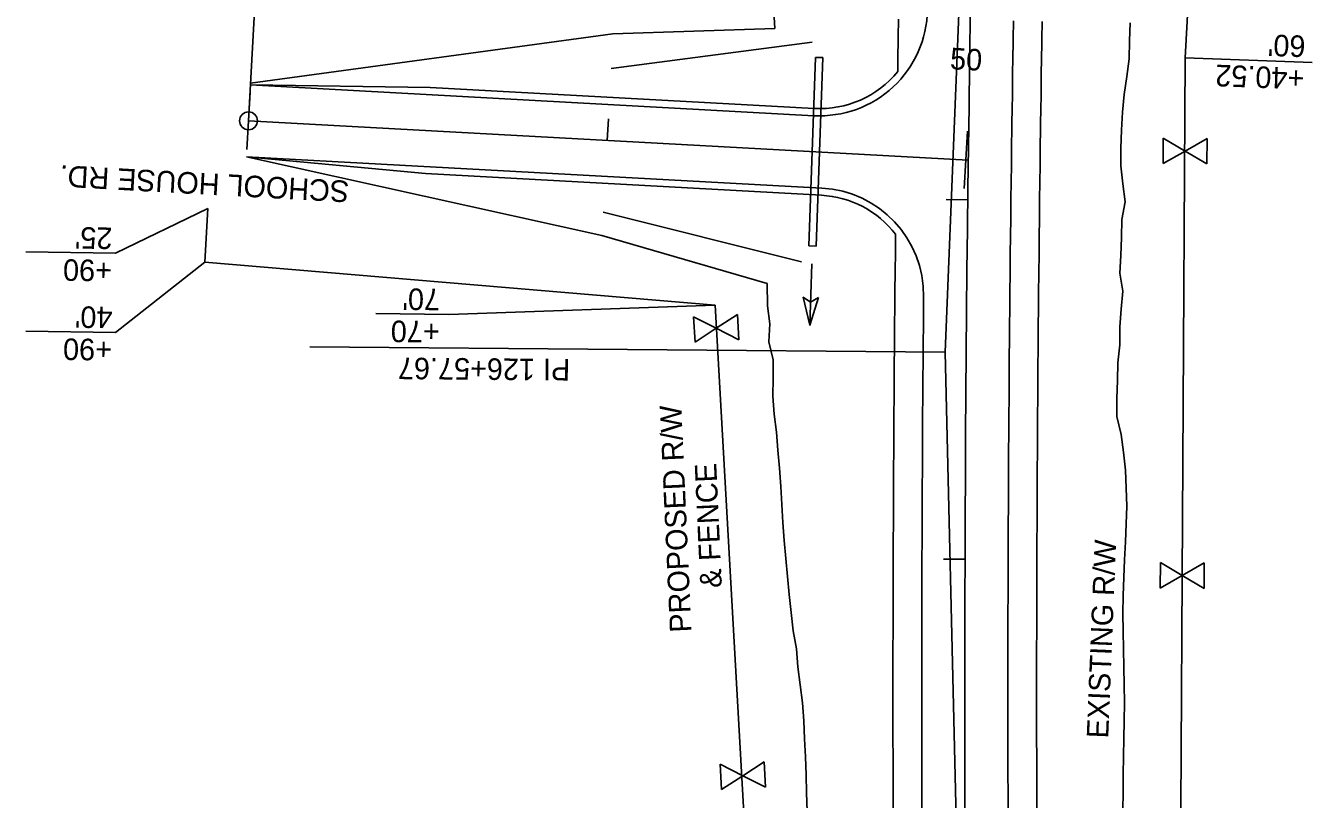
# Model space of a CAD drawing. Extents: x 634057 to 641016, y 287858 to 292331.
# Drawn here: x 634057.5 to 634415.7, y 291397.6 to 291613 of the extents above; entities that cross this region are included whole.
import ezdxf

# ---------------------------------------------------------------- set-up
doc = ezdxf.new("R2010")
doc.units = 0
for name, color, linetype in [('53', 7, 'Continuous'), ('PROPOSED SPECIAL DITCHES', 7, 'Continuous'), ('R_50 Horz Alg PC PI PT', 7, 'Continuous'), ('R_50 Horz Alg Stations', 7, 'Continuous'), ('R_50 Horz Alg Ticks', 7, 'Continuous'), ('R_Horz Alg', 7, 'Continuous'), ('R_No Plot', 7, 'Continuous'), ('R_Proposed Const Limits', 7, 'Continuous'), ('R_Proposed Road', 7, 'Continuous'), ('R_Proposed Shoulder', 7, 'Continuous'), ('R_ROW', 7, 'Continuous'), ('R_Water', 7, 'Continuous')]:
    doc.layers.add(name, color=color, linetype=linetype)

msp = doc.modelspace()

# ---------------------------------------------------------------- linework, layer by layer
at = {"layer": '53'}
for p, q in [((634415.68, 291602.72), (634380.33, 291604.07)), ((634108.17, 291562.09), (634082.44, 291549.65)), ((634082.44, 291549.65), (634057.49, 291550.03)), ((634107.36, 291547.11), (634082.44, 291527.61)), ((634175.28, 291532.62), (634154.97, 291532.84)), ((634249.46, 291535.15), (634175.28, 291532.62)), ((634082.44, 291527.61), (634057.49, 291527.99))]:
    msp.add_line(p, q, dxfattribs=at)
at = {"layer": 'PROPOSED SPECIAL DITCHES'}
for points in [[(634220.46, 291601.03), (634276.46, 291608.43)], [(634218.28, 291561.09), (634273.44, 291547.26)]]:
    msp.add_lwpolyline(points, dxfattribs=at)
at = {"layer": 'R_50 Horz Alg PC PI PT'}
for points in [[(634313.51, 291522.09), (634328.23, 291887.62)], [(634119.52, 291586.5), (634126.28, 291710.5)], [(634313.51, 291522.09), (634136.57, 291523.57)], [(634322.13, 291156.36), (634313.51, 291522.09)]]:
    msp.add_lwpolyline(points, dxfattribs=at)
msp.add_circle((634119.52, 291586.5), 2.5, dxfattribs=at)
at = {"layer": 'R_50 Horz Alg Ticks'}
for points in [[(634119.96, 291594.49), (634119.08, 291578.52)], [(634119.96, 291594.49), (634119.08, 291578.52)], [(634219.7, 291587.05), (634219.37, 291581.06)], [(634319.66, 291583.6), (634318.79, 291567.62)], [(634313.78, 291564.56), (634319.78, 291564.49)], [(634313.01, 291464.51), (634319.01, 291464.49)]]:
    msp.add_lwpolyline(points, dxfattribs=at)
at = {"layer": 'R_Horz Alg'}
msp.add_lwpolyline([(634319.92, 291575.57), (634119.52, 291586.5)], dxfattribs=at)
msp.add_arc((645778.1, 291426.39), 11459.16, 177.693224, 181.350269, dxfattribs=at)
at = {"layer": 'R_Proposed Const Limits'}
for points in [[(634266.02, 291612.22), (634265.87, 291615.38)], [(634220.99, 291610.74), (634120.07, 291596.99)], [(634220.99, 291610.74), (634266.02, 291612.22)], [(634365.01, 291613.75), (634364.83, 291608.78), (634364.73, 291603.8), (634364.04, 291598.82), (634363.35, 291593.85), (634362.88, 291588.88), (634362.53, 291583.9), (634362.42, 291578.92), (634362.38, 291573.94), (634362.93, 291568.95), (634363.57, 291563.96), (634362.71, 291558.99), (634362.57, 291554.01), (634362.34, 291549.03), (634362.08, 291544.05), (634362.98, 291539.06), (634362.5, 291534.09), (634362.07, 291529.11), (634362.15, 291524.13), (634361.58, 291519.15), (634361.46, 291514.17), (634361.28, 291509.19), (634361.23, 291504.21), (634362.46, 291499.22), (634363.1, 291494.23), (634363.64, 291489.25), (634363.88, 291484.27), (634364.05, 291479.28), (634363.86, 291474.3), (634363.64, 291469.32), (634363.45, 291464.34), (634363.23, 291459.36), (634363.02, 291454.38), (634362.92, 291449.4), (634363.01, 291444.42), (634363.1, 291439.44), (634363.2, 291434.46), (634363.3, 291429.48), (634363.4, 291424.5), (634363.33, 291419.52), (634363.23, 291414.54), (634363.14, 291409.56), (634363.07, 291404.58), (634363.04, 291399.6), (634362.98, 291394.62)], [(634217.93, 291554.57), (634118.98, 291576.52)], [(634217.93, 291554.57), (634263.91, 291541.25)], [(634275.07, 291394.37), (634274.91, 291399.39), (634274.77, 291404.41), (634274.56, 291409.43), (634274.29, 291414.45), (634274.16, 291419.47), (634273.8, 291424.49), (634273.13, 291429.51), (634272.46, 291434.53), (634272.12, 291439.55), (634271.2, 291444.57), (634270.58, 291449.59), (634270.06, 291454.61), (634269.6, 291459.64), (634269.1, 291464.66), (634268.61, 291469.68), (634268.25, 291474.71), (634268.03, 291479.73), (634267.75, 291484.75), (634267.34, 291489.78), (634266.93, 291494.8), (634266.48, 291499.83), (634265.84, 291504.86), (634265.51, 291509.88), (634265.56, 291514.9), (634265.55, 291519.93), (634264.35, 291524.96), (634264.62, 291529.98), (634264.01, 291535.01), (634263.91, 291541.25)]]:
    msp.add_lwpolyline(points, dxfattribs=at)
at = {"layer": 'R_Proposed Road'}
for points in [[(634330.99, 291394.53), (634330.98, 291399.52), (634330.97, 291404.52), (634330.96, 291409.51), (634330.95, 291414.5), (634330.95, 291414.51), (634330.95, 291419.5), (634330.95, 291424.49), (634330.95, 291429.49), (634330.95, 291434.48), (634330.95, 291435.99), (634330.95, 291439.48), (634330.96, 291444.47), (634330.97, 291449.47), (634330.98, 291454.46), (634330.99, 291457.47), (634330.99, 291459.46), (634331.01, 291464.45), (634331.03, 291469.45), (634331.05, 291474.44), (634331.07, 291478.96), (634331.07, 291479.44), (634331.09, 291484.43), (634331.12, 291489.43), (634331.15, 291494.42), (634331.18, 291499.42), (634331.18, 291500.45), (634331.21, 291504.41), (634331.25, 291509.4), (634331.28, 291514.4), (634331.32, 291519.39), (634331.34, 291521.94), (634331.36, 291524.39), (634331.41, 291529.38), (634331.45, 291534.38), (634331.5, 291539.37), (634331.54, 291543.43), (634331.55, 291544.37), (634331.61, 291549.36), (634331.66, 291554.36), (634331.72, 291559.35), (634331.78, 291564.34), (634331.78, 291564.92), (634331.84, 291569.34), (634331.9, 291574.33), (634331.97, 291579.33), (634332.03, 291584.32), (634332.06, 291586.41), (634332.1, 291589.32), (634332.18, 291594.31), (634332.25, 291599.3), (634332.33, 291604.3), (634332.38, 291607.89), (634332.41, 291609.29), (634332.49, 291614.29)], [(634276.91, 291587.93), (634120.07, 291596.49)], [(634279.12, 291567.78), (634118.98, 291576.52)], [(634306.99, 291394.46), (634306.98, 291399.46), (634306.97, 291404.47), (634306.96, 291409.48), (634306.95, 291414.47), (634306.95, 291414.48), (634306.95, 291419.49), (634306.95, 291424.49), (634306.95, 291429.5), (634306.95, 291434.5), (634306.95, 291436.01), (634306.95, 291439.51), (634306.96, 291444.51), (634306.97, 291449.52), (634306.98, 291454.52), (634306.99, 291457.54), (634306.99, 291459.53), (634307.01, 291464.53), (634307.03, 291469.54), (634307.05, 291474.54), (634307.07, 291479.07), (634307.07, 291479.55), (634307.09, 291484.55), (634307.12, 291489.56), (634307.15, 291494.56), (634307.18, 291499.57), (634307.19, 291500.61), (634307.21, 291504.57), (634307.25, 291509.58), (634307.28, 291514.58), (634307.32, 291519.59), (634307.35, 291522.14), (634307.37, 291524.59), (634307.41, 291529.6), (634307.46, 291534.6), (634307.48, 291537.54)]]:
    msp.add_lwpolyline(points, dxfattribs=at)
for centre, start, end in [((634278.54, 291617.89), 266.8777, 359.046), ((634277.49, 291537.83), 359.4449, 86.8777)]:
    msp.add_arc(centre, 30, start, end, dxfattribs=at)
at = {"layer": 'R_Proposed Shoulder'}
for points in [[(634300.26, 291600.22), (634300.33, 291604.8), (634300.39, 291608.4), (634300.41, 291609.8), (634300.49, 291614.81)], [(634338.99, 291394.55), (634338.98, 291399.54), (634338.97, 291404.53), (634338.96, 291409.52), (634338.95, 291414.5), (634338.95, 291414.51), (634338.95, 291419.5), (634338.95, 291424.5), (634338.95, 291429.49), (634338.95, 291434.48), (634338.95, 291435.98), (634338.95, 291439.47), (634338.96, 291444.46), (634338.97, 291449.45), (634338.98, 291454.44), (634338.99, 291457.45), (634338.99, 291459.43), (634339.01, 291464.43), (634339.03, 291469.42), (634339.05, 291474.41), (634339.07, 291478.93), (634339.07, 291479.4), (634339.09, 291484.39), (634339.12, 291489.38), (634339.15, 291494.37), (634339.18, 291499.36), (634339.18, 291500.4), (634339.21, 291504.36), (634339.25, 291509.35), (634339.28, 291514.34), (634339.32, 291519.33), (634339.34, 291521.88), (634339.36, 291524.32), (634339.41, 291529.31), (634339.45, 291534.3), (634339.5, 291539.29), (634339.54, 291543.35), (634339.55, 291544.28), (634339.61, 291549.28), (634339.66, 291554.27), (634339.72, 291559.26), (634339.78, 291564.25), (634339.78, 291564.82), (634339.84, 291569.24), (634339.9, 291574.23), (634339.97, 291579.22), (634340.03, 291584.21), (634340.06, 291586.29), (634340.1, 291589.2), (634340.18, 291594.19), (634340.25, 291599.18), (634340.33, 291604.17), (634340.38, 291607.77), (634340.41, 291609.17), (634340.49, 291614.16)], [(634170.1, 291595.76), (634120.07, 291596.49)], [(634277.01, 291589.93), (634170.1, 291595.76)], [(634168.79, 291571.8), (634118.98, 291576.52)], [(634279.01, 291565.79), (634168.79, 291571.8)], [(634298.99, 291394.44), (634298.98, 291399.45), (634298.97, 291404.45), (634298.96, 291409.46), (634298.95, 291414.46), (634298.95, 291414.47), (634298.95, 291419.48), (634298.95, 291424.49), (634298.95, 291429.5), (634298.95, 291434.51), (634298.95, 291436.01), (634298.95, 291439.52), (634298.96, 291444.52), (634298.97, 291449.53), (634298.98, 291454.54), (634298.99, 291457.56), (634298.99, 291459.55), (634299.01, 291464.56), (634299.03, 291469.57), (634299.05, 291474.58), (634299.07, 291479.11), (634299.07, 291479.59), (634299.09, 291484.59), (634299.12, 291489.6), (634299.15, 291494.61), (634299.18, 291499.62), (634299.19, 291500.66), (634299.21, 291504.63), (634299.25, 291509.64), (634299.28, 291514.65), (634299.32, 291519.65), (634299.35, 291522.21), (634299.37, 291524.66), (634299.41, 291529.67), (634299.46, 291534.68), (634299.5, 291539.69), (634299.55, 291543.76), (634299.56, 291544.7), (634299.61, 291549.71), (634299.66, 291554.71), (634299.66, 291554.92)]]:
    msp.add_lwpolyline(points, dxfattribs=at)
for centre, start, end in [((634278.54, 291617.89), 266.8777, 320.8759), ((634277.49, 291537.83), 37.6149, 86.8777)]:
    msp.add_arc(centre, 28, start, end, dxfattribs=at)
at = {"layer": 'R_ROW'}
for p, q in [((634374.13, 291574.59), (634374.19, 291581.66)), ((634374.19, 291581.66), (634380.28, 291578.07)), ((634380.28, 291578.07), (634386.43, 291581.56)), ((634386.43, 291581.56), (634386.37, 291574.49)), ((634380.28, 291578.07), (634374.13, 291574.59)), ((634386.37, 291574.49), (634380.28, 291578.07)), ((634243.43, 291531.92), (634249.75, 291528.74)), ((634243.84, 291524.86), (634243.43, 291531.92)), ((634249.75, 291528.74), (634255.66, 291532.62)), ((634255.66, 291532.62), (634256.06, 291525.56)), ((634249.75, 291528.74), (634243.84, 291524.86)), ((634256.06, 291525.56), (634249.75, 291528.74)), ((634373.33, 291456.45), (634373.39, 291463.53)), ((634373.39, 291463.53), (634379.48, 291459.94)), ((634379.48, 291459.94), (634385.63, 291463.43)), ((634385.63, 291463.43), (634385.58, 291456.35)), ((634379.48, 291459.94), (634373.33, 291456.45)), ((634385.58, 291456.35), (634379.48, 291459.94)), ((634250.84, 291407.38), (634257.15, 291404.2)), ((634251.24, 291400.32), (634250.84, 291407.38)), ((634257.15, 291404.2), (634263.06, 291408.08)), ((634263.06, 291408.08), (634263.47, 291401.02)), ((634257.15, 291404.2), (634251.24, 291400.32)), ((634263.47, 291401.02), (634257.15, 291404.2))]:
    msp.add_line(p, q, dxfattribs=at)
for points in [[(634404.32, 292161.54), (634388.9, 291762.53), (634380.33, 291604.07)], [(634380.33, 291604.07), (634379.04, 291379.12)], [(634107.36, 291547.11), (634108.17, 291562.09)], [(634249.46, 291535.15), (634107.36, 291547.11)], [(634240.21, 291255.58), (634259.11, 291364.17), (634249.46, 291535.15)]]:
    msp.add_lwpolyline(points, dxfattribs=at)
at = {"layer": 'R_Water'}
for points in [[(634277.42, 291604.17), (634275.54, 291551.7)], [(634279.42, 291604.1), (634277.42, 291604.17)], [(634279.42, 291604.1), (634277.54, 291551.63)], [(634277.54, 291551.63), (634275.54, 291551.7)], [(634275.8, 291529.58), (634276.38, 291546.7)]]:
    msp.add_lwpolyline(points, dxfattribs=at)
msp.add_lwpolyline([(634278.17, 291537.28), (634275.8, 291529.58), (634273.96, 291537.41), (634276.02, 291536.05)], close=True, dxfattribs=at)

# ---------------------------------------------------------------- texts
at = {"layer": '53'}
for s, rotation, p in [("60'  ", 177.8095, (634413.91, 291610.19)), ('+40.52 ', 177.8095, (634413.57, 291601.2)), ("25'  ", 179.1192, (634081.68, 291556.78)), ('+90 ', 179.1192, (634081.54, 291547.78)), ("70'  ", 179.364, (634172.87, 291539.76)), ("40'  ", 179.1192, (634081.68, 291534.74)), ('+70 ', 179.364, (634172.77, 291530.76)), ('+90 ', 179.1192, (634081.54, 291525.74)), ('PROPOSED R/W', 92.595, (634242.86, 291444.2)), ('& FENCE', 92.595, (634251.31, 291456.58)), ('EXISTING R/W', 87.6932, (634358.87, 291414.52))]:
    msp.add_text(s, height=6, rotation=rotation, dxfattribs=at).set_placement(p)
at = {"layer": 'R_50 Horz Alg PC PI PT'}
msp.add_text('PI 126+57.67', height=6, rotation=179.5217, dxfattribs=at).set_placement((634209.11, 291520.2))
at = {"layer": 'R_50 Horz Alg Stations'}
for s, rotation, p in [('50', 356.8777, (634314.71, 291600.89)), ('SCHOOL HOUSE RD.', 176.8777, (634147.68, 291569.78))]:
    msp.add_text(s, height=6, rotation=rotation, dxfattribs=at).set_placement(p)
at = {"layer": 'R_No Plot'}
for p in [(634119.47, 291586.46), (634119.47, 291586.46), (634319.18, 291575.56), (634319.87, 291575.52)]:
    msp.add_text('+', height=0.1, rotation=356.8777, dxfattribs=at).set_placement(p)

doc.saveas('drawing.dxf')
